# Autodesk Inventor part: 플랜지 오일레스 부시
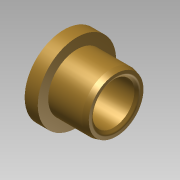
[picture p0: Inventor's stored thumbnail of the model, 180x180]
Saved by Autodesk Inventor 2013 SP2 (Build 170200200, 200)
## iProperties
Created: 2025-04
Part Number: 플랜지 오일레스 부시
Material: Generic
Document SubType Name: Modeling
Designer: i
Density: 1 g/cm^3
변환 표준: STEP AP214IS
전처리기: Build: 200, Release: 2013 SP2 Update 6 - Date: Thu 07/17/2014
전송 단위: 밀리미터
불확실성: 0.01
Author: i
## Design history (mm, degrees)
node "플랜지 오일레스 부시1"
node "솔리드1"
node "기준1"
